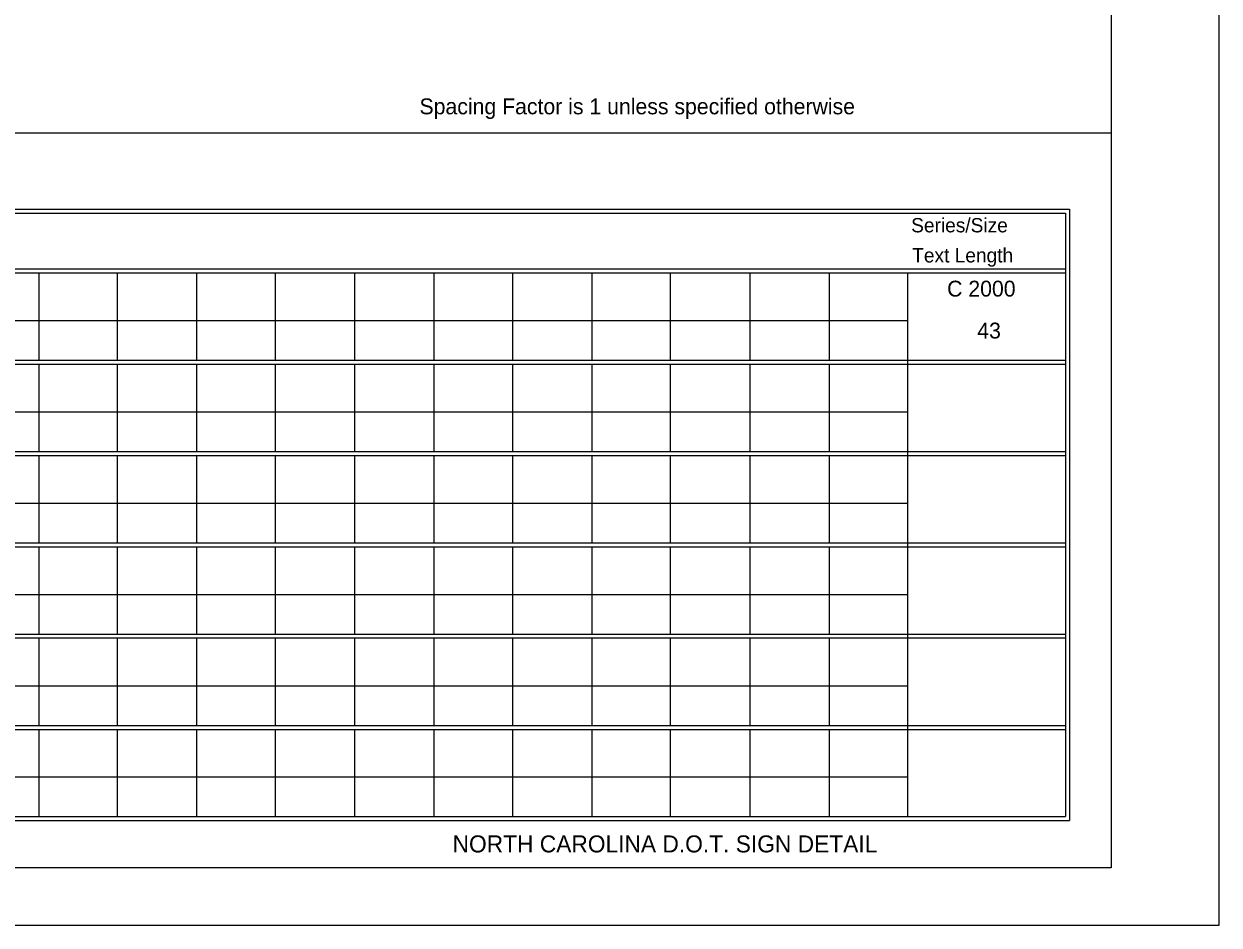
# Model space of a CAD drawing. Extents: x 1788.1 to 1851.2, y 237.2 to 283.4.
# Drawn here: x 1837.36 to 1851.19, y 237.17 to 247.6 of the extents above; entities that cross this region are included whole.
import ezdxf

# ---------------------------------------------------------------- set-up
doc = ezdxf.new("R2010")
doc.units = 0
doc.layers.add('Old_Level_2', color=7, linetype='Continuous')
doc.layers.add('Sheet Plot Border Outside CELL', color=7, linetype='Continuous')

msp = doc.modelspace()

# ---------------------------------------------------------------- linework, layer by layer
at = {"layer": 'Old_Level_2'}
for p, q in [((1832.78, 246.338), (1849.944, 246.338)), ((1821.981, 244.765), (1843.759, 244.765)), ((1821.981, 244.719), (1843.759, 244.719)), ((1837.536, 244.719), (1837.536, 243.709)), ((1838.444, 244.719), (1838.444, 243.709)), ((1839.363, 244.719), (1839.363, 243.709)), ((1840.272, 244.719), (1840.272, 243.709)), ((1841.19, 244.719), (1841.19, 243.709)), ((1842.108, 244.719), (1842.108, 243.709)), ((1842.785, 244.765), (1849.417, 244.765)), ((1842.785, 244.719), (1849.417, 244.719)), ((1843.017, 244.719), (1843.017, 243.709)), ((1843.017, 244.719), (1843.017, 243.709)), ((1843.935, 244.719), (1843.935, 243.709)), ((1844.844, 244.719), (1844.844, 243.709)), ((1845.763, 244.719), (1845.763, 243.709)), ((1846.681, 244.719), (1846.681, 243.709)), ((1847.59, 244.719), (1847.59, 238.595)), ((1822.9, 244.168), (1843.759, 244.168)), ((1842.785, 244.168), (1847.59, 244.168)), ((1847.59, 243.959), (1847.59, 243.709)), ((1821.981, 243.709), (1843.759, 243.709)), ((1842.785, 243.709), (1849.417, 243.709)), ((1821.981, 243.663), (1843.759, 243.663)), ((1837.536, 243.663), (1837.536, 242.652)), ((1838.444, 243.663), (1838.444, 242.652)), ((1839.363, 243.663), (1839.363, 242.652)), ((1840.272, 243.663), (1840.272, 242.652)), ((1841.19, 243.663), (1841.19, 242.652)), ((1842.108, 243.663), (1842.108, 242.652)), ((1842.785, 243.663), (1849.417, 243.663)), ((1843.017, 243.663), (1843.017, 242.652)), ((1843.017, 243.663), (1843.017, 242.652)), ((1843.935, 243.663), (1843.935, 242.652)), ((1844.844, 243.663), (1844.844, 242.652)), ((1845.763, 243.663), (1845.763, 242.652)), ((1846.681, 243.663), (1846.681, 242.652)), ((1847.59, 243.663), (1847.59, 243.183)), ((1822.9, 243.112), (1843.759, 243.112)), ((1842.785, 243.112), (1847.59, 243.112)), ((1847.59, 242.981), (1847.59, 242.652)), ((1821.981, 242.652), (1843.759, 242.652)), ((1821.981, 242.606), (1843.759, 242.606)), ((1837.536, 242.606), (1837.536, 241.596)), ((1838.444, 242.606), (1838.444, 241.596)), ((1839.363, 242.606), (1839.363, 241.596)), ((1840.272, 242.606), (1840.272, 241.596)), ((1841.19, 242.606), (1841.19, 241.596)), ((1842.108, 242.606), (1842.108, 241.596)), ((1842.785, 242.652), (1849.417, 242.652)), ((1842.785, 242.606), (1849.417, 242.606)), ((1843.017, 242.606), (1843.017, 241.596)), ((1843.017, 242.606), (1843.017, 241.596)), ((1843.935, 242.606), (1843.935, 241.596)), ((1844.844, 242.606), (1844.844, 241.596)), ((1845.763, 242.606), (1845.763, 241.596)), ((1846.681, 242.606), (1846.681, 241.596)), ((1847.59, 242.606), (1847.59, 242.196)), ((1822.9, 242.055), (1843.759, 242.055)), ((1842.785, 242.055), (1847.59, 242.055)), ((1847.59, 241.894), (1847.59, 241.596)), ((1821.981, 241.596), (1843.759, 241.596)), ((1821.981, 241.55), (1843.759, 241.55)), ((1837.536, 241.55), (1837.536, 240.54)), ((1838.444, 241.55), (1838.444, 240.54)), ((1839.363, 241.55), (1839.363, 240.54)), ((1840.272, 241.55), (1840.272, 240.54)), ((1841.19, 241.55), (1841.19, 240.54)), ((1842.108, 241.55), (1842.108, 240.54)), ((1842.785, 241.596), (1849.417, 241.596)), ((1842.785, 241.55), (1849.417, 241.55)), ((1843.017, 241.55), (1843.017, 240.54)), ((1843.017, 241.55), (1843.017, 240.54)), ((1843.935, 241.55), (1843.935, 240.54)), ((1844.844, 241.55), (1844.844, 240.54)), ((1845.763, 241.55), (1845.763, 240.54)), ((1846.681, 241.55), (1846.681, 240.54)), ((1847.59, 241.55), (1847.59, 241.107)), ((1822.9, 240.999), (1843.759, 240.999)), ((1842.785, 240.999), (1847.59, 240.999)), ((1847.59, 240.805), (1847.59, 240.54)), ((1837.536, 240.657), (1837.536, 240.54)), ((1838.444, 240.657), (1838.444, 240.54)), ((1839.363, 240.657), (1839.363, 240.54)), ((1840.272, 240.657), (1840.272, 240.54)), ((1841.19, 240.657), (1841.19, 240.54)), ((1842.108, 240.657), (1842.108, 240.54)), ((1843.017, 240.657), (1843.017, 240.54)), ((1843.017, 240.657), (1843.017, 240.54)), ((1843.935, 240.657), (1843.935, 240.54)), ((1844.844, 240.657), (1844.844, 240.54)), ((1845.763, 240.657), (1845.763, 240.54)), ((1846.681, 240.657), (1846.681, 240.54)), ((1847.59, 240.657), (1847.59, 240.54)), ((1821.981, 240.54), (1843.759, 240.54)), ((1821.981, 240.54), (1843.759, 240.54)), ((1821.981, 240.494), (1843.759, 240.494)), ((1821.981, 240.494), (1843.759, 240.494)), ((1837.536, 240.494), (1837.536, 239.549)), ((1837.536, 240.494), (1837.536, 239.483)), ((1838.444, 240.494), (1838.444, 239.549)), ((1838.444, 240.494), (1838.444, 239.483)), ((1839.363, 240.494), (1839.363, 239.549)), ((1839.363, 240.494), (1839.363, 239.483)), ((1840.272, 240.494), (1840.272, 239.549)), ((1840.272, 240.494), (1840.272, 239.483)), ((1841.19, 240.494), (1841.19, 239.549)), ((1841.19, 240.494), (1841.19, 239.483)), ((1842.108, 240.494), (1842.108, 239.549)), ((1842.108, 240.494), (1842.108, 239.483)), ((1842.785, 240.54), (1849.417, 240.54)), ((1842.785, 240.54), (1849.417, 240.54)), ((1842.785, 240.494), (1849.417, 240.494)), ((1842.785, 240.494), (1849.417, 240.494)), ((1843.017, 240.494), (1843.017, 239.549)), ((1843.017, 240.494), (1843.017, 239.483)), ((1843.017, 240.494), (1843.017, 239.549)), ((1843.017, 240.494), (1843.017, 239.483)), ((1843.935, 240.494), (1843.935, 239.549)), ((1843.935, 240.494), (1843.935, 239.483)), ((1844.844, 240.494), (1844.844, 239.549)), ((1844.844, 240.494), (1844.844, 239.483)), ((1845.763, 240.494), (1845.763, 239.549)), ((1845.763, 240.494), (1845.763, 239.483)), ((1846.681, 240.494), (1846.681, 239.549)), ((1846.681, 240.494), (1846.681, 239.483)), ((1847.59, 240.494), (1847.59, 240.039)), ((1847.59, 240.494), (1847.59, 240.039)), ((1822.9, 239.942), (1843.759, 239.942)), ((1822.9, 239.942), (1843.759, 239.942)), ((1842.785, 239.942), (1847.59, 239.942)), ((1842.785, 239.942), (1847.352, 239.942)), ((1847.59, 239.777), (1847.59, 239.549)), ((1847.59, 239.777), (1847.59, 239.483)), ((1837.536, 239.601), (1837.536, 239.483)), ((1838.444, 239.601), (1838.444, 239.483)), ((1839.363, 239.601), (1839.363, 239.483)), ((1840.272, 239.601), (1840.272, 239.483)), ((1841.19, 239.601), (1841.19, 239.483)), ((1842.108, 239.601), (1842.108, 239.483)), ((1843.017, 239.601), (1843.017, 239.483)), ((1843.017, 239.601), (1843.017, 239.483)), ((1843.935, 239.601), (1843.935, 239.483)), ((1844.844, 239.601), (1844.844, 239.483)), ((1845.763, 239.601), (1845.763, 239.483)), ((1846.681, 239.601), (1846.681, 239.483)), ((1847.59, 239.601), (1847.59, 239.483)), ((1821.981, 239.483), (1843.759, 239.483)), ((1821.981, 239.483), (1843.759, 239.483)), ((1821.981, 239.437), (1843.759, 239.437)), ((1821.981, 239.437), (1843.759, 239.437)), ((1837.536, 239.437), (1837.536, 238.427)), ((1837.536, 239.437), (1837.536, 238.427)), ((1838.444, 239.437), (1838.444, 238.427)), ((1838.444, 239.437), (1838.444, 238.427)), ((1839.363, 239.437), (1839.363, 238.427)), ((1839.363, 239.437), (1839.363, 238.427)), ((1840.272, 239.437), (1840.272, 238.427)), ((1840.272, 239.437), (1840.272, 238.427)), ((1841.19, 239.437), (1841.19, 238.427)), ((1841.19, 239.437), (1841.19, 238.427)), ((1842.108, 239.437), (1842.108, 238.427)), ((1842.108, 239.437), (1842.108, 238.427)), ((1842.785, 239.483), (1849.417, 239.483)), ((1842.785, 239.483), (1849.417, 239.483)), ((1842.785, 239.437), (1849.417, 239.437)), ((1842.785, 239.437), (1849.417, 239.437)), ((1843.017, 239.437), (1843.017, 238.427)), ((1843.017, 239.437), (1843.017, 238.427)), ((1843.017, 239.437), (1843.017, 238.427)), ((1843.017, 239.437), (1843.017, 238.427)), ((1843.935, 239.437), (1843.935, 238.427)), ((1843.935, 239.437), (1843.935, 238.427)), ((1844.844, 239.437), (1844.844, 238.427)), ((1844.844, 239.437), (1844.844, 238.427)), ((1845.763, 239.437), (1845.763, 238.427)), ((1845.763, 239.437), (1845.763, 238.427)), ((1846.681, 239.437), (1846.681, 238.427)), ((1846.681, 239.437), (1846.681, 238.427)), ((1847.59, 239.437), (1847.59, 239.012)), ((1847.59, 239.437), (1847.59, 239.012)), ((1822.9, 238.886), (1843.759, 238.886)), ((1822.9, 238.886), (1843.759, 238.886)), ((1842.785, 238.886), (1847.59, 238.886)), ((1842.785, 238.886), (1847.414, 238.886)), ((1847.59, 238.689), (1847.59, 238.427)), ((1847.59, 238.689), (1847.59, 238.427)), ((1821.981, 238.427), (1843.759, 238.427)), ((1821.981, 238.427), (1843.759, 238.427)), ((1842.785, 238.427), (1849.417, 238.427)), ((1842.785, 238.427), (1849.417, 238.427)), ((1821.934, 238.381), (1843.759, 238.381)), ((1821.981, 238.381), (1843.759, 238.381)), ((1842.785, 238.381), (1849.464, 238.381)), ((1842.785, 238.381), (1849.417, 238.381))]:
    msp.add_line(p, q, dxfattribs=at)
msp.add_lwpolyline([(1821.618, 257.479), (1849.944, 257.479), (1849.944, 237.834), (1821.618, 237.834)], close=True, dxfattribs=at)
for points in [[(1821.934, 239.549), (1821.934, 245.454), (1843.759, 245.454)], [(1821.981, 239.549), (1821.981, 245.408), (1843.759, 245.408)], [(1842.785, 245.454), (1849.464, 245.454), (1849.464, 239.549)], [(1842.785, 245.408), (1849.417, 245.408), (1849.417, 239.549)], [(1849.417, 240.657), (1849.417, 238.427)], [(1849.464, 240.657), (1849.464, 238.381)]]:
    msp.add_lwpolyline(points, dxfattribs=at)
at = {"layer": 'Sheet Plot Border Outside CELL'}
msp.add_lwpolyline([(1851.194, 258.025), (1821.023, 258.025), (1821.023, 237.172), (1851.194, 237.172)], close=True, dxfattribs=at)

# ---------------------------------------------------------------- texts
at = {"layer": 'Old_Level_2'}
for s, height, p in [('Spacing Factor is 1 unless specified otherwise', 0.18373, (1841.942, 246.553)), ('Series/Size', 0.16535, (1847.631, 245.187)), ('Text Length', 0.16535, (1847.643, 244.839)), ('NORTH CAROLINA D.O.T. SIGN DETAIL', 0.19685, (1842.325, 238.013))]:
    msp.add_text(s, height=height, rotation=360, dxfattribs=at).set_placement(p)
for s, p in [('C 2000', (1848.047, 244.444)), ('43', (1848.396, 243.959))]:
    msp.add_text(s, height=0.1837, dxfattribs=at).set_placement(p)

doc.saveas('drawing.dxf')
